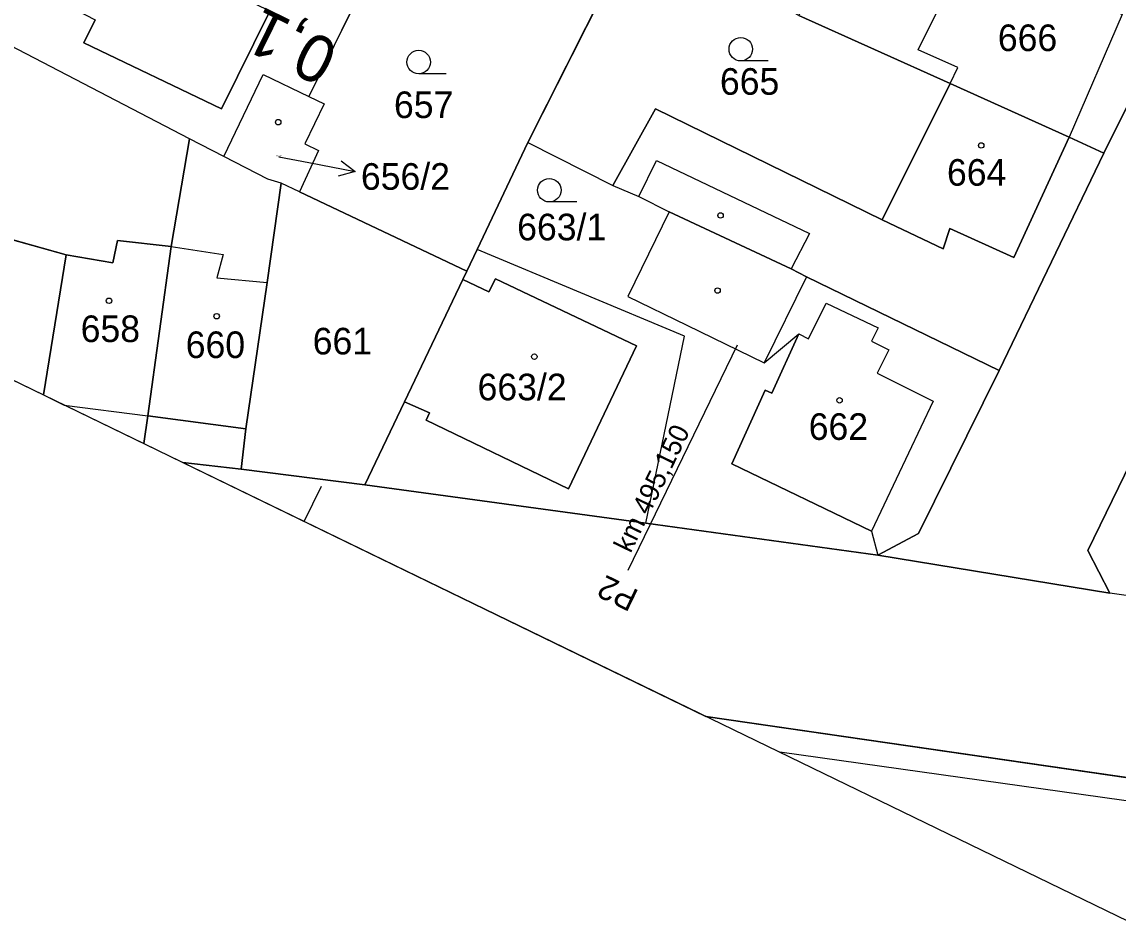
# Model space of a CAD drawing. Extents: x -762314 to -761449, y -993181 to -992589.
# Drawn here: x -761953.9 to -761883.9, y -993023 to -992965.6 of the extents above; entities that cross this region are included whole.
import ezdxf

# ---------------------------------------------------------------- set-up
doc = ezdxf.new("R2010")
doc.units = 0
for name, color, linetype in [('Formáty', 7, 'Continuous'), ('Hranice - vnitř_ kresba', 7, 'Continuous'), ('Hranice parcel', 7, 'Continuous'), ('Obvody jako plochy', 7, 'Continuous'), ('Parcelní čísla', 7, 'Continuous'), ('Prvky pro prodl_ par_ č_', 7, 'Continuous'), ('SO1010_příčné řezy', 7, 'Continuous'), ('Vrstva 7', 7, 'Continuous'), ('Značky kultur', 7, 'Continuous'), ('Značky na budově ne v SPI', 7, 'Continuous'), ('Značky na budově v SPI', 7, 'Continuous')]:
    doc.layers.add(name, color=color, linetype=linetype)

msp = doc.modelspace()

# ---------------------------------------------------------------- linework, layer by layer
at = {"layer": 'Formáty'}
msp.add_line((-761935.861, -992997.538), (-761934.769, -992995.289), dxfattribs=at)
msp.add_lwpolyline([(-761558.019, -993180.938), (-762313.703, -992814.139), (-762204.471, -992589.097), (-761448.787, -992955.896)], close=True, dxfattribs=at)
msp.add_lwpolyline([(-761558.019, -993180.938), (-762313.703, -992814.139), (-762204.471, -992589.097), (-761448.787, -992955.896)], close=True, dxfattribs=at)
at = {"layer": 'Hranice - vnitř_ kresba'}
for p, q in [((-761896.645, -992967.416), (-761893.235, -992960.516)), ((-761938.055, -992964.926), (-761941.145, -992971.186)), ((-761949.945, -992966.966), (-761949.215, -992965.486)), ((-761883.615, -992965.146), (-761887.015, -992972.976)), ((-761941.145, -992971.186), (-761949.945, -992966.966)), ((-761894.115, -992968.526), (-761896.645, -992967.416)), ((-761894.605, -992969.566), (-761894.115, -992968.526)), ((-761887.015, -992972.976), (-761890.535, -992980.666)), ((-761914.485, -992976.776), (-761913.375, -992974.476)), ((-761913.375, -992974.476), (-761903.595, -992979.146)), ((-761895.055, -992980.116), (-761898.955, -992978.266)), ((-761894.635, -992978.816), (-761895.055, -992980.116)), ((-761890.535, -992980.666), (-761894.635, -992978.816)), ((-761948.085, -992981.016), (-761947.785, -992979.596)), ((-761947.785, -992979.596), (-761944.365, -992979.976)), ((-761903.595, -992979.146), (-761904.775, -992981.396)), ((-761944.365, -992979.976), (-761941.035, -992980.486)), ((-761951.065, -992980.506), (-761948.085, -992981.016)), ((-761941.035, -992980.486), (-761941.455, -992981.966)), ((-761941.455, -992981.966), (-761938.235, -992982.266)), ((-761925.735, -992982.086), (-761924.065, -992982.876)), ((-761924.065, -992982.876), (-761923.655, -992982.026)), ((-761923.655, -992982.026), (-761914.635, -992986.326)), ((-761903.775, -992981.916), (-761906.485, -992987.396)), ((-761903.665, -992985.866), (-761902.525, -992983.586)), ((-761902.525, -992983.586), (-761899.205, -992985.166)), ((-761899.205, -992985.166), (-761899.625, -992986.016)), ((-761904.285, -992985.556), (-761903.665, -992985.866)), ((-761914.635, -992986.326), (-761918.985, -992995.446)), ((-761899.625, -992986.016), (-761898.525, -992986.566)), ((-761898.525, -992986.566), (-761899.265, -992988.056)), ((-761899.265, -992988.056), (-761895.685, -992989.846)), ((-761951.189, -992990.098), (-761945.865, -992990.796)), ((-761927.855, -992990.606), (-761929.465, -992989.886)), ((-761895.685, -992989.846), (-761899.635, -992998.156)), ((-761945.865, -992990.796), (-761939.585, -992991.616)), ((-761928.075, -992991.066), (-761927.855, -992990.606)), ((-761918.985, -992995.446), (-761928.075, -992991.066))]:
    msp.add_line(p, q, dxfattribs=at)
at = {"layer": 'Hranice parcel'}
for p, q in [((-761929.125, -992957.366), (-761935.575, -992970.386)), ((-761916.635, -992963.516), (-761921.585, -992973.316)), ((-761879.915, -992964.176), (-761884.785, -992974.016)), ((-761894.605, -992969.566), (-761904.285, -992965.216)), ((-761943.185, -992973.086), (-761955.185, -992966.856)), ((-761940.995, -992974.216), (-761938.495, -992968.986)), ((-761938.495, -992968.986), (-761935.575, -992970.386)), ((-761894.605, -992969.566), (-761898.955, -992978.266)), ((-761887.015, -992972.976), (-761894.605, -992969.566)), ((-761935.575, -992970.386), (-761934.595, -992970.856)), ((-761934.595, -992970.856), (-761935.835, -992973.416)), ((-761913.435, -992971.166), (-761916.155, -992976.076)), ((-761898.955, -992978.266), (-761913.435, -992971.166)), ((-761944.365, -992979.976), (-761943.185, -992973.086)), ((-761940.995, -992974.216), (-761943.185, -992973.086)), ((-761921.585, -992973.316), (-761924.825, -992980.156)), ((-761921.585, -992973.316), (-761916.155, -992976.076)), ((-761884.785, -992974.016), (-761887.015, -992972.976)), ((-761934.955, -992973.846), (-761936.175, -992976.476)), ((-761935.835, -992973.416), (-761934.955, -992973.846)), ((-761884.785, -992974.016), (-761891.485, -992987.896)), ((-761938.185, -992975.666), (-761940.995, -992974.216)), ((-761937.345, -992975.916), (-761938.235, -992982.266)), ((-761937.345, -992975.916), (-761938.185, -992975.666)), ((-761936.175, -992976.476), (-761937.345, -992975.916)), ((-761916.155, -992976.076), (-761914.485, -992976.776)), ((-761925.485, -992981.556), (-761936.175, -992976.476)), ((-761914.485, -992976.776), (-761912.555, -992977.766)), ((-761951.065, -992980.506), (-761960.365, -992977.906)), ((-761912.555, -992977.766), (-761915.195, -992983.166)), ((-761912.555, -992977.766), (-761904.775, -992981.396)), ((-761945.865, -992990.796), (-761944.365, -992979.976)), ((-761924.825, -992980.156), (-761925.485, -992981.556)), ((-761911.585, -992985.706), (-761924.825, -992980.156)), ((-761952.511, -992989.457), (-761951.065, -992980.506)), ((-761925.485, -992981.556), (-761925.735, -992982.086)), ((-761904.775, -992981.396), (-761903.775, -992981.916)), ((-761885.825, -992999.396), (-761877.235, -992981.766)), ((-761938.235, -992982.266), (-761939.585, -992991.616)), ((-761925.735, -992982.086), (-761929.465, -992989.886)), ((-761903.775, -992981.916), (-761891.485, -992987.896)), ((-761915.195, -992983.166), (-761911.435, -992984.986)), ((-761911.435, -992984.986), (-761906.485, -992987.396)), ((-761914.055, -992997.656), (-761911.585, -992985.706)), ((-761906.485, -992987.396), (-761904.285, -992985.556)), ((-761904.285, -992985.556), (-761905.995, -992989.346)), ((-761891.485, -992987.896), (-761896.635, -992998.296)), ((-761906.425, -992989.156), (-761908.545, -992993.846)), ((-761905.995, -992989.346), (-761906.425, -992989.156)), ((-761929.465, -992989.886), (-761931.995, -992995.186)), ((-761946.11, -992992.564), (-761945.865, -992990.796)), ((-761939.885, -992994.206), (-761939.585, -992991.616)), ((-761943.625, -992993.77), (-761939.885, -992994.206)), ((-761939.885, -992994.206), (-761931.995, -992995.186)), ((-761908.545, -992993.846), (-761899.635, -992998.156)), ((-761931.995, -992995.186), (-761914.055, -992997.656)), ((-761914.055, -992997.656), (-761899.235, -992999.696)), ((-761899.635, -992998.156), (-761899.235, -992999.696)), ((-761896.635, -992998.296), (-761899.235, -992999.696)), ((-761899.235, -992999.696), (-761884.415, -993002.116)), ((-761884.415, -993002.116), (-761885.825, -992999.396)), ((-761870.915, -993004.046), (-761884.415, -993002.116)), ((-761860.085, -993017.276), (-761910.21, -993009.989)), ((-761862.145, -993018.366), (-761905.483, -993012.284))]:
    msp.add_line(p, q, dxfattribs=at)
at = {"layer": 'Obvody jako plochy'}
for p, q in [((-761896.645, -992967.416), (-761893.235, -992960.516)), ((-761938.055, -992964.926), (-761941.145, -992971.186)), ((-761949.945, -992966.966), (-761949.215, -992965.486)), ((-761883.615, -992965.146), (-761887.015, -992972.976)), ((-761941.145, -992971.186), (-761949.945, -992966.966)), ((-761894.115, -992968.526), (-761896.645, -992967.416)), ((-761940.995, -992974.216), (-761938.495, -992968.986)), ((-761938.495, -992968.986), (-761935.575, -992970.386)), ((-761894.605, -992969.566), (-761894.115, -992968.526)), ((-761894.605, -992969.566), (-761898.955, -992978.266)), ((-761887.015, -992972.976), (-761894.605, -992969.566)), ((-761887.015, -992972.976), (-761894.605, -992969.566)), ((-761935.575, -992970.386), (-761934.595, -992970.856)), ((-761934.595, -992970.856), (-761935.835, -992973.416)), ((-761887.015, -992972.976), (-761890.535, -992980.666)), ((-761934.955, -992973.846), (-761936.175, -992976.476)), ((-761935.835, -992973.416), (-761934.955, -992973.846)), ((-761938.185, -992975.666), (-761940.995, -992974.216)), ((-761937.345, -992975.916), (-761938.185, -992975.666)), ((-761936.175, -992976.476), (-761937.345, -992975.916)), ((-761895.055, -992980.116), (-761898.955, -992978.266)), ((-761894.635, -992978.816), (-761895.055, -992980.116)), ((-761890.535, -992980.666), (-761894.635, -992978.816)), ((-761948.085, -992981.016), (-761947.785, -992979.596)), ((-761947.785, -992979.596), (-761944.365, -992979.976)), ((-761945.865, -992990.796), (-761944.365, -992979.976)), ((-761945.865, -992990.796), (-761944.365, -992979.976)), ((-761944.365, -992979.976), (-761941.035, -992980.486)), ((-761952.511, -992989.457), (-761951.065, -992980.506)), ((-761951.065, -992980.506), (-761948.085, -992981.016)), ((-761941.035, -992980.486), (-761941.455, -992981.966)), ((-761941.455, -992981.966), (-761938.235, -992982.266)), ((-761938.235, -992982.266), (-761939.585, -992991.616)), ((-761925.735, -992982.086), (-761929.465, -992989.886)), ((-761925.735, -992982.086), (-761924.065, -992982.876)), ((-761924.065, -992982.876), (-761923.655, -992982.026)), ((-761923.655, -992982.026), (-761914.635, -992986.326)), ((-761903.665, -992985.866), (-761902.525, -992983.586)), ((-761902.525, -992983.586), (-761899.205, -992985.166)), ((-761963.446, -992984.149), (-761952.511, -992989.457)), ((-761899.205, -992985.166), (-761899.625, -992986.016)), ((-761904.285, -992985.556), (-761905.995, -992989.346)), ((-761904.285, -992985.556), (-761903.665, -992985.866)), ((-761914.635, -992986.326), (-761918.985, -992995.446)), ((-761899.625, -992986.016), (-761898.525, -992986.566)), ((-761898.525, -992986.566), (-761899.265, -992988.056)), ((-761899.265, -992988.056), (-761895.685, -992989.846)), ((-761952.511, -992989.457), (-761946.11, -992992.564)), ((-761952.511, -992989.457), (-761951.189, -992990.098)), ((-761906.425, -992989.156), (-761908.545, -992993.846)), ((-761905.995, -992989.346), (-761906.425, -992989.156)), ((-761951.189, -992990.098), (-761945.865, -992990.796)), ((-761927.855, -992990.606), (-761929.465, -992989.886)), ((-761895.685, -992989.846), (-761899.635, -992998.156)), ((-761945.865, -992990.796), (-761939.585, -992991.616)), ((-761928.075, -992991.066), (-761927.855, -992990.606)), ((-761918.985, -992995.446), (-761928.075, -992991.066)), ((-761946.11, -992992.564), (-761943.625, -992993.77)), ((-761943.625, -992993.77), (-761910.21, -993009.989)), ((-761908.545, -992993.846), (-761899.635, -992998.156))]:
    msp.add_line(p, q, dxfattribs=at)
for points in [[(-761871.705, -992942.296), (-761858.805, -992948.846), (-761861.795, -992949.776), (-761866.845, -992960.376), (-761868.945, -992964.786), (-761877.235, -992981.766), (-761885.825, -992999.396), (-761884.415, -993002.116), (-761899.235, -992999.696), (-761896.635, -992998.296), (-761891.485, -992987.896), (-761884.785, -992974.016), (-761879.915, -992964.176), (-761878.125, -992960.046), (-761871.185, -992945.616), (-761870.705, -992944.936)], [(-761948.975, -992960.416), (-761950.995, -992964.576), (-761949.215, -992965.486), (-761949.945, -992966.966), (-761941.145, -992971.186), (-761938.055, -992964.926), (-761940.805, -992963.566), (-761937.555, -992956.936), (-761945.145, -992953.276), (-761946.685, -992956.486), (-761948.655, -992960.566)], [(-761901.785, -992960.166), (-761904.285, -992965.216), (-761894.605, -992969.566), (-761887.015, -992972.976), (-761884.785, -992974.016), (-761879.915, -992964.176), (-761894.085, -992956.996), (-761899.145, -992954.606)], [(-761916.635, -992963.516), (-761929.125, -992957.366), (-761935.575, -992970.386), (-761934.595, -992970.856), (-761935.835, -992973.416), (-761934.955, -992973.846), (-761936.175, -992976.476), (-761925.485, -992981.556), (-761924.825, -992980.156), (-761921.585, -992973.316)], [(-761904.285, -992965.216), (-761914.795, -992959.526), (-761916.635, -992963.516), (-761921.585, -992973.316), (-761916.155, -992976.076), (-761913.435, -992971.166), (-761898.955, -992978.266), (-761894.605, -992969.566)], [(-761896.645, -992967.416), (-761893.235, -992960.516), (-761883.615, -992965.146), (-761887.015, -992972.976), (-761894.605, -992969.566), (-761894.115, -992968.526)], [(-761937.345, -992975.916), (-761938.185, -992975.666), (-761940.995, -992974.216), (-761938.495, -992968.986), (-761935.575, -992970.386), (-761934.595, -992970.856), (-761935.835, -992973.416), (-761934.955, -992973.846), (-761936.175, -992976.476)], [(-761913.435, -992971.166), (-761916.155, -992976.076), (-761914.485, -992976.776), (-761912.555, -992977.766), (-761904.775, -992981.396), (-761903.775, -992981.916), (-761891.485, -992987.896), (-761884.785, -992974.016), (-761887.015, -992972.976), (-761894.605, -992969.566), (-761898.955, -992978.266)], [(-761894.605, -992969.566), (-761898.955, -992978.266), (-761895.055, -992980.116), (-761894.635, -992978.816), (-761890.535, -992980.666), (-761887.015, -992972.976)], [(-761911.435, -992984.986), (-761906.485, -992987.396), (-761904.285, -992985.556), (-761905.995, -992989.346), (-761906.425, -992989.156), (-761908.545, -992993.846), (-761899.635, -992998.156), (-761899.235, -992999.696), (-761914.055, -992997.656), (-761911.585, -992985.706), (-761924.825, -992980.156), (-761921.585, -992973.316), (-761916.155, -992976.076), (-761914.485, -992976.776), (-761912.555, -992977.766), (-761915.195, -992983.166)], [(-761936.175, -992976.476), (-761937.345, -992975.916), (-761938.235, -992982.266), (-761939.585, -992991.616), (-761939.885, -992994.206), (-761931.995, -992995.186), (-761929.465, -992989.886), (-761925.735, -992982.086), (-761925.485, -992981.556)], [(-761905.995, -992989.346), (-761906.425, -992989.156), (-761908.545, -992993.846), (-761899.635, -992998.156), (-761899.235, -992999.696), (-761896.635, -992998.296), (-761891.485, -992987.896), (-761903.775, -992981.916), (-761904.775, -992981.396), (-761912.555, -992977.766), (-761915.195, -992983.166), (-761911.435, -992984.986), (-761906.485, -992987.396), (-761904.285, -992985.556)], [(-761941.035, -992980.486), (-761941.455, -992981.966), (-761938.235, -992982.266), (-761939.585, -992991.616), (-761945.865, -992990.796), (-761944.365, -992979.976)], [(-761925.485, -992981.556), (-761925.735, -992982.086), (-761929.465, -992989.886), (-761931.995, -992995.186), (-761914.055, -992997.656), (-761911.585, -992985.706), (-761924.825, -992980.156)], [(-761863.085, -992988.916), (-761859.615, -992990.686), (-761861.145, -992993.676), (-761864.685, -992992.016), (-761870.915, -993004.046), (-761884.415, -993002.116), (-761885.825, -992999.396), (-761877.235, -992981.766), (-761874.635, -992983.016), (-761869.185, -992985.916)], [(-761925.735, -992982.086), (-761929.465, -992989.886), (-761927.855, -992990.606), (-761928.075, -992991.066), (-761918.985, -992995.446), (-761914.635, -992986.326), (-761923.655, -992982.026), (-761924.065, -992982.876)], [(-761899.625, -992986.016), (-761898.525, -992986.566), (-761899.265, -992988.056), (-761895.685, -992989.846), (-761899.635, -992998.156), (-761908.545, -992993.846), (-761906.425, -992989.156), (-761905.995, -992989.346), (-761904.285, -992985.556), (-761903.665, -992985.866), (-761902.525, -992983.586), (-761899.205, -992985.166)]]:
    msp.add_lwpolyline(points, close=True, dxfattribs=at)
for points in [[(-761946.11, -992992.564), (-761945.865, -992990.796), (-761944.365, -992979.976), (-761943.185, -992973.086), (-761955.185, -992966.856), (-761960.365, -992977.906), (-761951.065, -992980.506), (-761952.511, -992989.457)], [(-761943.625, -992993.77), (-761939.885, -992994.206), (-761939.585, -992991.616), (-761938.235, -992982.266), (-761937.345, -992975.916), (-761938.185, -992975.666), (-761940.995, -992974.216), (-761943.185, -992973.086), (-761944.365, -992979.976), (-761945.865, -992990.796), (-761946.11, -992992.564)], [(-761952.511, -992989.457), (-761951.065, -992980.506), (-761960.365, -992977.906), (-761963.446, -992984.149)], [(-761951.189, -992990.098), (-761945.865, -992990.796), (-761944.365, -992979.976), (-761947.785, -992979.596), (-761948.085, -992981.016), (-761951.065, -992980.506), (-761952.511, -992989.457)], [(-761910.21, -993009.989), (-761860.085, -993017.276), (-761827.045, -993022.076), (-761794.655, -993026.786), (-761794.565, -993025.896), (-761793.765, -993018.286), (-761793.635, -993017.046), (-761793.425, -993015.006), (-761813.375, -993012.036), (-761826.955, -993010.056), (-761837.965, -993008.456), (-761859.025, -993005.656), (-761870.915, -993004.046), (-761884.415, -993002.116), (-761899.235, -992999.696), (-761914.055, -992997.656), (-761931.995, -992995.186), (-761939.885, -992994.206), (-761943.625, -992993.77)]]:
    msp.add_lwpolyline(points, dxfattribs=at)
at = {"layer": 'Prvky pro prodl_ par_ č_'}
for p, q in [((-761937.485, -992974.236), (-761935.565, -992974.606)), ((-761935.565, -992974.606), (-761932.62, -992975.181))]:
    msp.add_line(p, q, dxfattribs=at)
msp.add_lwpolyline([(-761933.506, -992974.499), (-761932.62, -992975.181), (-761933.698, -992975.48)], dxfattribs=at)
at = {"layer": 'SO1010_příčné řezy'}
msp.add_lwpolyline([(-761915.175, -993000.648), (-761908.189, -992986.254)], dxfattribs=at)
at = {"layer": 'Značky kultur'}
for p, q in [((-761906.235, -992968.116), (-761907.985, -992968.116)), ((-761926.805, -992968.936), (-761928.555, -992968.936)), ((-761918.465, -992977.126), (-761920.215, -992977.126))]:
    msp.add_line(p, q, dxfattribs=at)
for centre in [(-761907.985, -992967.366), (-761928.555, -992968.186), (-761920.215, -992976.376)]:
    msp.add_circle(centre, 0.75, dxfattribs=at)
at = {"layer": 'Značky na budově ne v SPI'}
for centre in [(-761909.275, -992977.986), (-761909.465, -992982.786)]:
    msp.add_circle(centre, 0.175, dxfattribs=at)
at = {"layer": 'Značky na budově v SPI'}
for centre in [(-761937.525, -992972.026), (-761892.625, -992973.516), (-761948.335, -992983.436), (-761941.455, -992984.426), (-761921.165, -992987.006), (-761901.675, -992989.796)]:
    msp.add_circle(centre, 0.175, dxfattribs=at)

# ---------------------------------------------------------------- texts
at = {"layer": 'Parcelní čísla'}
for s, height, p in [('666', 1.7, (-761891.565, -992967.486)), ('665', 1.7, (-761909.315, -992970.276)), ('657', 1.7, (-761930.135, -992971.766)), ('656/2', 0.1, (-761937.669, -992974.236)), ('664', 1.7, (-761894.815, -992976.086)), ('663/1', 1.7, (-761922.265, -992979.576)), ('658', 1.7, (-761950.145, -992986.076)), ('661', 1.7, (-761935.325, -992986.866)), ('660', 1.7, (-761943.435, -992987.096)), ('663/2', 1.7, (-761924.795, -992989.796)), ('662', 1.7, (-761903.645, -992992.326))]:
    msp.add_text(s, height=height, dxfattribs=at).set_placement(p)
at = {"layer": 'Prvky pro prodl_ par_ č_'}
msp.add_text('656/2', height=1.7, dxfattribs=at).set_placement((-761932.245, -992976.346))
at = {"layer": 'SO1010_příčné řezy'}
for s, height, rotation, p in [('km 495,150', 1.25, 64.10867, (-761915.02, -992999.612)), ('P2', 1.5, 154.19867, (-761914.421, -993001.985))]:
    msp.add_text(s, height=height, rotation=rotation, dxfattribs=at).set_placement(p)
at = {"layer": 'Vrstva 7'}
msp.add_text('0,1', height=3, rotation=153.80758, dxfattribs=at).set_placement((-761933.513, -992967.093))

doc.saveas('drawing.dxf')
